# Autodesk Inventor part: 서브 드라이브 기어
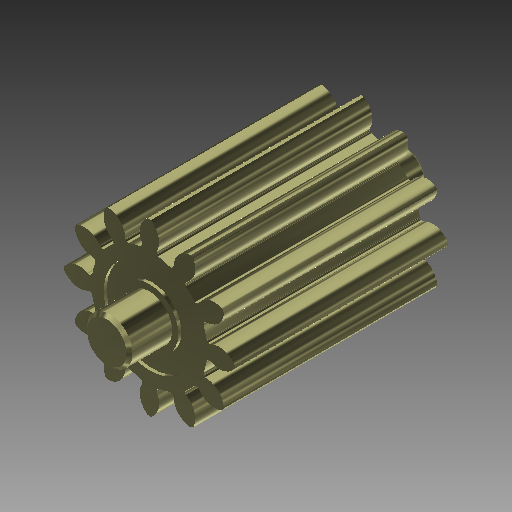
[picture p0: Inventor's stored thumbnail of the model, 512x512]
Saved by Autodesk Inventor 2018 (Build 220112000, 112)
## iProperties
Created: 2013-07
Part Number: 서브 드라이브 기어
Document SubType Name: Modeling
Designer: 한국산업디자인학원
Density: 1 g/cm^3
Mass: 123.501 g
Surface Area: 265.416 cm^2
Volume: 123.501 cm^3
Material: 강철, 탄소
Appearance: 반광택(1)
변환 표준: STEP AP214IS
파일 이름: C:\Documents and Settings\?댁씪諛곗?1\諛뷀깢 ?붾㈃\2013-07-27 ?덉긽臾몄젣\媛?몄삩 援ъ꽦?붿냼\留ㅺ컻蹂??MZ)?섏젙?섎㈃ ?먮룞? 留뚮뱾?댁????ㅽ띁湲곗뼱.stp
전처리기: Build: 223b, Release: 2010 RTM - Date: Sat 02/14/2009
전송 단위: 밀리미터
불확실성: 0.01
Author: 한국산업디자인학원
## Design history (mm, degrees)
sketch "스케치1"
  geometry: A1 r 6 centre (-2.816, 23.011) between (2.462, 20.157) and (0.524, 27.995) reference; A2 r 28 centre (0, 0) between (0.524, 27.995) and (-0.524, 27.995) reference; A3 r 6 centre (2.816, 23.011) between (-0.524, 27.995) and (-2.462, 20.157) reference; A4 r 0.972 centre (-3.318, 19.695) between (-3.156, 18.736) and (-2.462, 20.157) reference; A5 r 19 centre (0, 0) between (-3.156, 18.736) and (-6.635, 17.804) reference; A6 r 0.972 centre (-6.974, 18.715) between (-7.946, 18.688) and (-6.635, 17.804) reference; A7 r 6 centre (-13.944, 18.52) between (-7.946, 18.688) and (-13.544, 24.506) reference; A8 r 28 centre (0, 0) between (-13.544, 24.506) and (-14.451, 23.983) reference; A9 r 6 centre (-9.067, 21.336) between (-14.451, 23.983) and (-12.211, 16.226) reference; A10 r 0.972 centre (-12.721, 15.397) between (-12.101, 14.648) and (-12.211, 16.226) reference; A11 r 19 centre (0, 0) between (-12.101, 14.648) and (-14.648, 12.101) reference; A12 r 0.972 centre (-15.397, 12.721) between (-16.226, 12.211) and (-14.648, 12.101) reference; A13 r 6 centre (-21.336, 9.067) between (-16.226, 12.211) and (-23.983, 14.451) reference; A14 r 28 centre (0, 0) between (-23.983, 14.451) and (-24.506, 13.544) reference; A15 r 6 centre (-18.52, 13.944) between (-24.506, 13.544) and (-18.688, 7.946) reference; A16 r 0.972 centre (-18.715, 6.974) between (-17.804, 6.635) and (-18.688, 7.946) reference; A17 r 19 centre (0, 0) between (-17.804, 6.635) and (-18.736, 3.156) reference; A18 r 0.972 centre (-19.695, 3.318) between (-20.157, 2.462) and (-18.736, 3.156) reference; A19 r 6 centre (-23.011, -2.816) between (-20.157, 2.462) and (-27.995, 0.524) reference; A20 r 28 centre (0, 0) between (-27.995, 0.524) and (-27.995, -0.524) reference; A21 r 6 centre (-23.011, 2.816) between (-27.995, -0.524) and (-20.157, -2.462) reference; A22 r 0.972 centre (-19.695, -3.318) between (-18.736, -3.156) and (-20.157, -2.462) reference; A23 r 19 centre (0, 0) between (-18.736, -3.156) and (-17.804, -6.635) reference; A24 r 0.972 centre (-18.715, -6.974) between (-18.688, -7.946) and (-17.804, -6.635) reference; A25 r 6 centre (-18.52, -13.944) between (-18.688, -7.946) and (-24.506, -13.544) reference; A26 r 28 centre (0, 0) between (-24.506, -13.544) and (-23.983, -14.451) reference; A27 r 6 centre (-21.336, -9.067) between (-23.983, -14.451) and (-16.226, -12.211) reference; A28 r 0.972 centre (-15.397, -12.721) between (-14.648, -12.101) and (-16.226, -12.211) reference; A29 r 19 centre (0, 0) between (-14.648, -12.101) and (-12.101, -14.648) reference; A30 r 0.972 centre (-12.721, -15.397) between (-12.211, -16.226) and (-12.101, -14.648) reference; A31 r 6 centre (-9.067, -21.336) between (-12.211, -16.226) and (-14.451, -23.983) reference; A32 r 28 centre (0, 0) between (-14.451, -23.983) and (-13.544, -24.506) reference; A33 r 6 centre (-13.944, -18.52) between (-13.544, -24.506) and (-7.946, -18.688) reference; A34 r 0.972 centre (-6.974, -18.715) between (-6.635, -17.804) and (-7.946, -18.688) reference; A35 r 19 centre (0, 0) between (-6.635, -17.804) and (-3.156, -18.736) reference; A36 r 0.972 centre (-3.318, -19.695) between (-2.462, -20.157) and (-3.156, -18.736) reference; A37 r 6 centre (2.816, -23.011) between (-2.462, -20.157) and (-0.524, -27.995) reference; A38 r 28 centre (0, 0) between (-0.524, -27.995) and (0.524, -27.995) reference; A39 r 6 centre (-2.816, -23.011) between (0.524, -27.995) and (2.462, -20.157) reference; A40 r 0.972 centre (3.318, -19.695) between (3.156, -18.736) and (2.462, -20.157) reference; A41 r 19 centre (0, 0) between (3.156, -18.736) and (6.635, -17.804) reference; A42 r 0.972 centre (6.974, -18.715) between (7.946, -18.688) and (6.635, -17.804) reference; A43 r 6 centre (13.944, -18.52) between (7.946, -18.688) and (13.544, -24.506) reference; A44 r 28 centre (0, 0) between (13.544, -24.506) and (14.451, -23.983) reference; A45 r 6 centre (9.067, -21.336) between (14.451, -23.983) and (12.211, -16.226) reference; A46 r 0.972 centre (12.721, -15.397) between (12.101, -14.648) and (12.211, -16.226) reference; A47 r 19 centre (0, 0) between (12.101, -14.648) and (14.648, -12.101) reference; A48 r 0.972 centre (15.397, -12.721) between (16.226, -12.211) and (14.648, -12.101) reference; A49 r 6 centre (21.336, -9.067) between (16.226, -12.211) and (23.983, -14.451) reference; A50 r 28 centre (0, 0) between (23.983, -14.451) and (24.506, -13.544) reference; A51 r 6 centre (18.52, -13.944) between (24.506, -13.544) and (18.688, -7.946) reference; A52 r 0.972 centre (18.715, -6.974) between (17.804, -6.635) and (18.688, -7.946) reference; A53 r 19 centre (0, 0) between (17.804, -6.635) and (18.736, -3.156) reference; A54 r 0.972 centre (19.695, -3.318) between (20.157, -2.462) and (18.736, -3.156) reference; A55 r 6 centre (23.011, 2.816) between (20.157, -2.462) and (27.995, -0.524) reference; A56 r 28 centre (0, 0) between (27.995, -0.524) and (27.995, 0.524) reference; A57 r 6 centre (23.011, -2.816) between (27.995, 0.524) and (20.157, 2.462) reference; A58 r 0.972 centre (19.695, 3.318) between (18.736, 3.156) and (20.157, 2.462) reference; A59 r 19 centre (0, 0) between (18.736, 3.156) and (17.804, 6.635) reference; A60 r 0.972 centre (18.715, 6.974) between (18.688, 7.946) and (17.804, 6.635) reference; A61 r 6 centre (18.52, 13.944) between (18.688, 7.946) and (24.506, 13.544) reference; A62 r 28 centre (0, 0) between (24.506, 13.544) and (23.983, 14.451) reference; A63 r 6 centre (21.336, 9.067) between (23.983, 14.451) and (16.226, 12.211) reference; A64 r 0.972 centre (15.397, 12.721) between (14.648, 12.101) and (16.226, 12.211) reference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; 1 further point
extrude "돌출1" new body sketch "스케치1" stored distance "d0" = 70; taper "d1" = 0 deg
sketch "스케치2"
  geometry: C1 r 7.5 at (0, 0); 1 further point
  constraints: 1 centre point, 1 coincident
  dimensions: "d2" = 15 diameter of C1
extrude "돌출2" join sketch "스케치2" distance "d3" = 14; taper "d4" = 0 deg
chamfer "모따기1" distance "d5" = 1; stored, may be unused: second distance "d6" = 2, angle "d7" = 45 deg
node "작업 평면1"
sketch "스케치3"
  geometry: C1 r 9.5 at (0, 0); C2 r 15 at (0, 0); 1 further point
  constraints: 2 centre point, 2 coincident
  dimensions: "d8" = 19 diameter of C1; "d9" = 30 diameter of C2
extrude "돌출3" cut sketch "스케치3" distance "d10" = 1; taper "d11" = 0 deg
node "솔리드4"
mirror "대칭1"
mirror "대칭2"
node "투영된 루프1"
node "솔리드2"
